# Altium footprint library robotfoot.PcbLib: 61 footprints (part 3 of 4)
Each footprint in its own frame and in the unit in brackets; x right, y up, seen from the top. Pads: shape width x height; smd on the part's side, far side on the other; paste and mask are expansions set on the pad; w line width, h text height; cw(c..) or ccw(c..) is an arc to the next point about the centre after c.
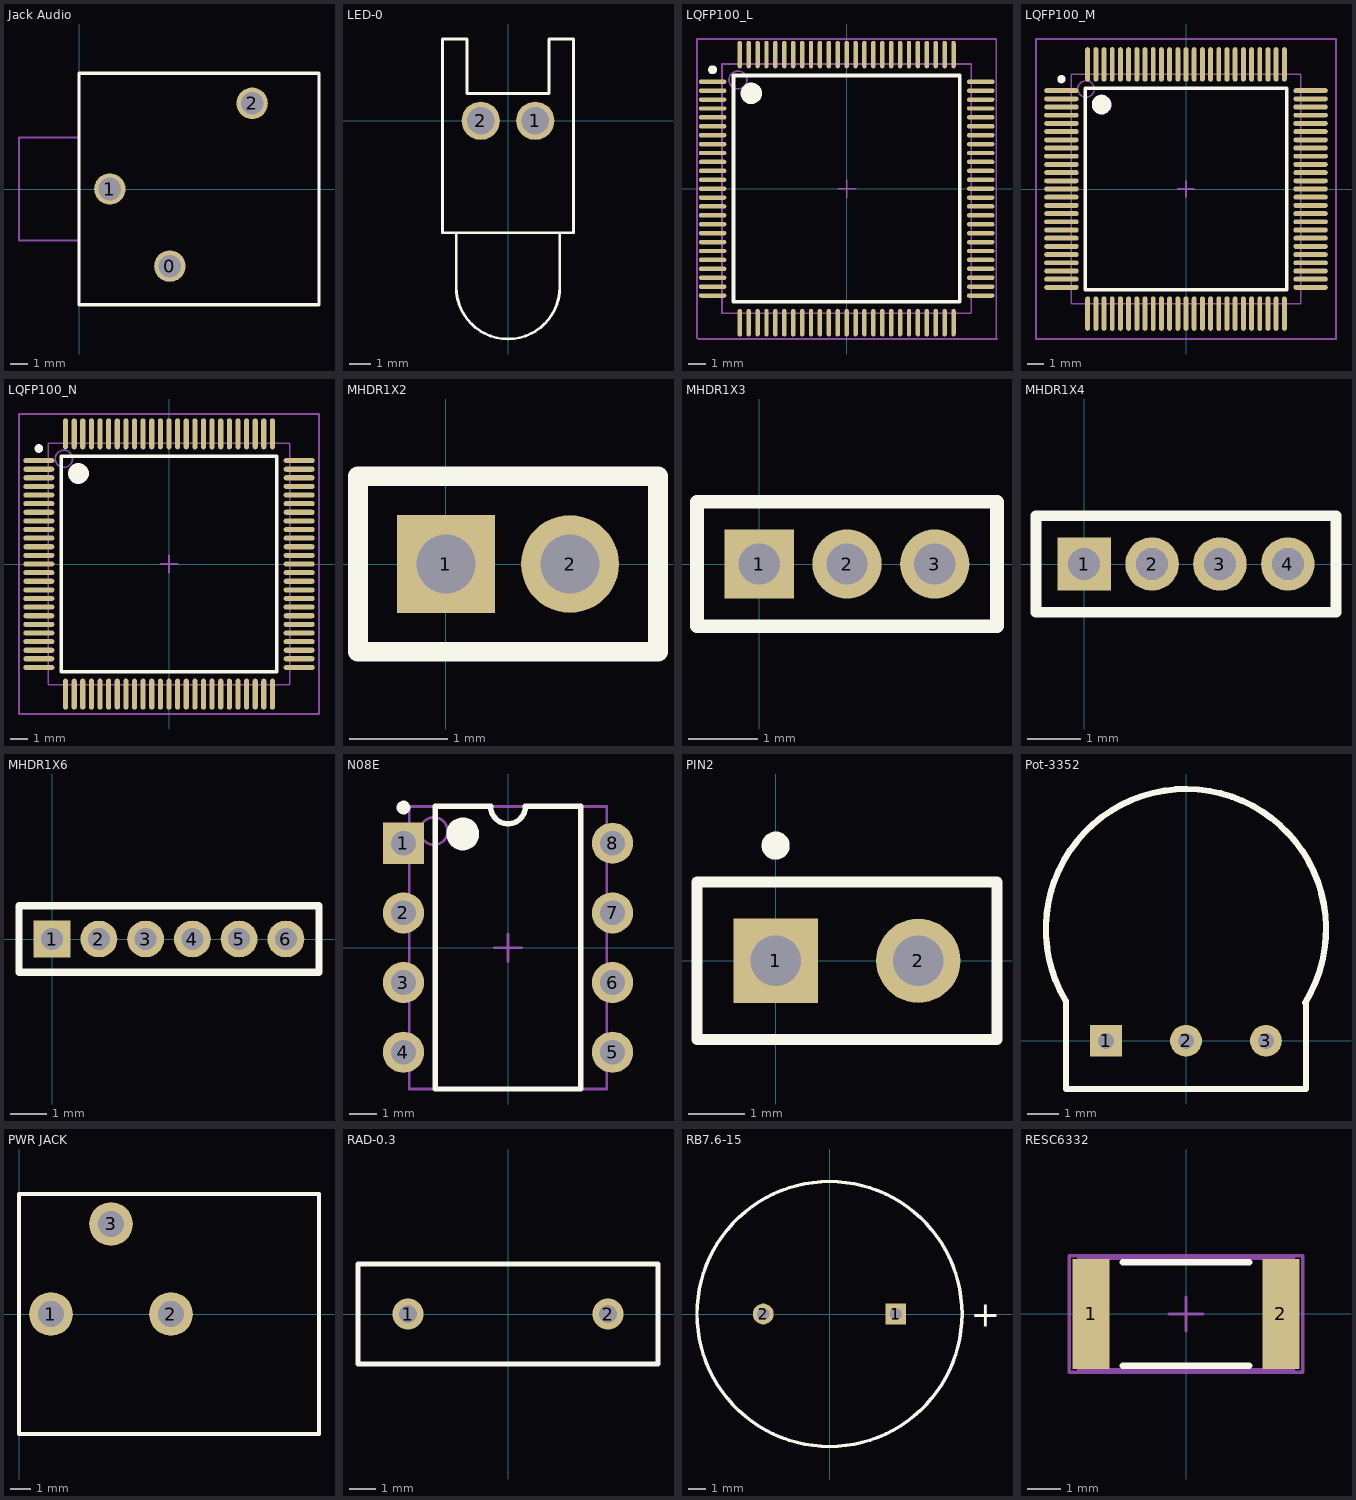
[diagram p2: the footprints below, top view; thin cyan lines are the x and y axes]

## Jack Audio [mil] "Connector; Stereo Jack 3.5mm"
height 157.48
pads (3):
  round 72 hole 52: 0(208.66,-177.17) 1(70.87,0) 2(397.64,196.85)
Top Overlay:
  lines w7.87: 0,-265.75 0,265.75 551.18,265.75 551.18,-265.75 0,-265.75
Mechanical 13:
  lines w3.94: -137.8,-118.11 0,-118.11 0,-265.75 551.18,-265.75 551.18,265.75 0,265.75 0,118.11 -137.8,118.11 -137.8,-118.11

## LED-0 [mil] "LED; 2 Leads"
pads (2):
  round 70 hole 50: 1(50,0) 2(-50,0)
Top Overlay:
  lines w5: -95,-205 -95,-305 ccw(c0,-305) 95,-305 95,-205 ; -120,-205 120,-205 120,150 75,150 75,50 -75,50 -75,150 -120,150 -120,-205

## LQFP100_L [mm] "Thin QFP, 100-Leads, Body 14x14mm, Pitch 0.5mm, IPC High Density"
height 1.6
pads (100):
  oval 1.55x0.25 smd: 1(-7.525,6) 2(-7.525,5.5) 3(-7.525,5) 4(-7.525,4.5) 5(-7.525,4) 6(-7.525,3.5) 7(-7.525,3) 8(-7.525,2.5) 9(-7.525,2) 10(-7.525,1.5) 11(-7.525,1) 12(-7.525,0.5) 13(-7.525,0) 14(-7.525,-0.5) 15(-7.525,-1) 16(-7.525,-1.5) 17(-7.525,-2) 18(-7.525,-2.5) 19(-7.525,-3) 20(-7.525,-3.5) 21(-7.525,-4) 22(-7.525,-4.5) 23(-7.525,-5) 24(-7.525,-5.5) 25(-7.525,-6) 51(7.525,-6) 52(7.525,-5.5) 53(7.525,-5) 54(7.525,-4.5) 55(7.525,-4) 56(7.525,-3.5) 57(7.525,-3) 58(7.525,-2.5) 59(7.525,-2) 60(7.525,-1.5) 61(7.525,-1) 62(7.525,-0.5) 63(7.525,0) 64(7.525,0.5) 65(7.525,1) 66(7.525,1.5) 67(7.525,2) 68(7.525,2.5) 69(7.525,3) 70(7.525,3.5) 71(7.525,4) 72(7.525,4.5) 73(7.525,5) 74(7.525,5.5) 75(7.525,6)
  oval 0.25x1.55 smd: 26(-6,-7.525) 27(-5.5,-7.525) 28(-5,-7.525) 29(-4.5,-7.525) 30(-4,-7.525) 31(-3.5,-7.525) 32(-3,-7.525) 33(-2.5,-7.525) 34(-2,-7.525) 35(-1.5,-7.525) 36(-1,-7.525) 37(-0.5,-7.525) 38(0,-7.525) 39(0.5,-7.525) 40(1,-7.525) 41(1.5,-7.525) 42(2,-7.525) 43(2.5,-7.525) 44(3,-7.525) 45(3.5,-7.525) 46(4,-7.525) 47(4.5,-7.525) 48(5,-7.525) 49(5.5,-7.525) 50(6,-7.525) 76(6,7.525) 77(5.5,7.525) 78(5,7.525) 79(4.5,7.525) 80(4,7.525) 81(3.5,7.525) 82(3,7.525) 83(2.5,7.525) 84(2,7.525) 85(1.5,7.525) 86(1,7.525) 87(0.5,7.525) 88(0,7.525) 89(-0.5,7.525) 90(-1,7.525) 91(-1.5,7.525) 92(-2,7.525) 93(-2.5,7.525) 94(-3,7.525) 95(-3.5,7.525) 96(-4,7.525) 97(-4.5,7.525) 98(-5,7.525) 99(-5.5,7.525) 100(-6,7.525)
Top Overlay:
  circle w0.25: c-7.525,6.675 r0.125
  circle w0.6: c-5.35,5.35 r0.3
  lines w0.2: -6.35,-6.35 -6.35,6.35 6.35,6.35 6.35,-6.35 -6.35,-6.35
Mechanical 13:
  circle w0.1: c-6.1,6.1 r0.5
  lines w0.1: -7,-7 -7,7 7,7 7,-7 -7,-7
Mechanical 15:
  lines w0.1: -8.4,-8.4 -8.4,8.4 8.4,8.4 8.4,-8.4 ; -8.36,-8.44 8.44,-8.44 ; -0.5,0 0.5,0 ; 0,-0.5 0,0.5
3D body: height 1.6, standoff 0, extent -7,-7 7,7

## LQFP100_M [mm] "Thin QFP, 100-Leads, Body 14x14mm, Pitch 0.5mm, IPC Low Density"
height 1.6
pads (100):
  oval 2.1x0.3 smd: 1(-7.6,6) 2(-7.6,5.5) 3(-7.6,5) 4(-7.6,4.5) 5(-7.6,4) 6(-7.6,3.5) 7(-7.6,3) 8(-7.6,2.5) 9(-7.6,2) 10(-7.6,1.5) 11(-7.6,1) 12(-7.6,0.5) 13(-7.6,0) 14(-7.6,-0.5) 15(-7.6,-1) 16(-7.6,-1.5) 17(-7.6,-2) 18(-7.6,-2.5) 19(-7.6,-3) 20(-7.6,-3.5) 21(-7.6,-4) 22(-7.6,-4.5) 23(-7.6,-5) 24(-7.6,-5.5) 25(-7.6,-6) 51(7.6,-6) 52(7.6,-5.5) 53(7.6,-5) 54(7.6,-4.5) 55(7.6,-4) 56(7.6,-3.5) 57(7.6,-3) 58(7.6,-2.5) 59(7.6,-2) 60(7.6,-1.5) 61(7.6,-1) 62(7.6,-0.5) 63(7.6,0) 64(7.6,0.5) 65(7.6,1) 66(7.6,1.5) 67(7.6,2) 68(7.6,2.5) 69(7.6,3) 70(7.6,3.5) 71(7.6,4) 72(7.6,4.5) 73(7.6,5) 74(7.6,5.5) 75(7.6,6)
  oval 0.3x2.1 smd: 26(-6,-7.6) 27(-5.5,-7.6) 28(-5,-7.6) 29(-4.5,-7.6) 30(-4,-7.6) 31(-3.5,-7.6) 32(-3,-7.6) 33(-2.5,-7.6) 34(-2,-7.6) 35(-1.5,-7.6) 36(-1,-7.6) 37(-0.5,-7.6) 38(0,-7.6) 39(0.5,-7.6) 40(1,-7.6) 41(1.5,-7.6) 42(2,-7.6) 43(2.5,-7.6) 44(3,-7.6) 45(3.5,-7.6) 46(4,-7.6) 47(4.5,-7.6) 48(5,-7.6) 49(5.5,-7.6) 50(6,-7.6) 76(6,7.6) 77(5.5,7.6) 78(5,7.6) 79(4.5,7.6) 80(4,7.6) 81(3.5,7.6) 82(3,7.6) 83(2.5,7.6) 84(2,7.6) 85(1.5,7.6) 86(1,7.6) 87(0.5,7.6) 88(0,7.6) 89(-0.5,7.6) 90(-1,7.6) 91(-1.5,7.6) 92(-2,7.6) 93(-2.5,7.6) 94(-3,7.6) 95(-3.5,7.6) 96(-4,7.6) 97(-4.5,7.6) 98(-5,7.6) 99(-5.5,7.6) 100(-6,7.6)
Top Overlay:
  circle w0.6: c-5.15,5.15 r0.3
  circle w0.25: c-7.6,6.7 r0.125
  lines w0.2: -6.15,-6.15 6.15,-6.15 6.15,6.15 -6.15,6.15 -6.15,-6.15
Mechanical 13:
  circle w0.1: c-6.1,6.1 r0.5
  lines w0.1: -7,-7 7,-7 7,7 -7,7 -7,-7
Mechanical 15:
  lines w0.1: -0.5,0 0.5,0 ; 0,-0.5 0,0.5 ; -9.15,-9.15 9.15,-9.15 9.15,9.15 -9.15,9.15 -9.15,-9.15
3D body: height 1.6, standoff 0, extent -7,-7 7,7

## LQFP100_N [mm] "Thin QFP, 100-Leads, Body 14x14mm, Pitch 0.5mm, IPC Medium Density"
height 1.6
pads (100):
  oval 1.8x0.3 smd: 1(-7.55,6) 2(-7.55,5.5) 3(-7.55,5) 4(-7.55,4.5) 5(-7.55,4) 6(-7.55,3.5) 7(-7.55,3) 8(-7.55,2.5) 9(-7.55,2) 10(-7.55,1.5) 11(-7.55,1) 12(-7.55,0.5) 13(-7.55,0) 14(-7.55,-0.5) 15(-7.55,-1) 16(-7.55,-1.5) 17(-7.55,-2) 18(-7.55,-2.5) 19(-7.55,-3) 20(-7.55,-3.5) 21(-7.55,-4) 22(-7.55,-4.5) 23(-7.55,-5) 24(-7.55,-5.5) 25(-7.55,-6) 51(7.55,-6) 52(7.55,-5.5) 53(7.55,-5) 54(7.55,-4.5) 55(7.55,-4) 56(7.55,-3.5) 57(7.55,-3) 58(7.55,-2.5) 59(7.55,-2) 60(7.55,-1.5) 61(7.55,-1) 62(7.55,-0.5) 63(7.55,0) 64(7.55,0.5) 65(7.55,1) 66(7.55,1.5) 67(7.55,2) 68(7.55,2.5) 69(7.55,3) 70(7.55,3.5) 71(7.55,4) 72(7.55,4.5) 73(7.55,5) 74(7.55,5.5) 75(7.55,6)
  oval 0.3x1.8 smd: 26(-6,-7.55) 27(-5.5,-7.55) 28(-5,-7.55) 29(-4.5,-7.55) 30(-4,-7.55) 31(-3.5,-7.55) 32(-3,-7.55) 33(-2.5,-7.55) 34(-2,-7.55) 35(-1.5,-7.55) 36(-1,-7.55) 37(-0.5,-7.55) 38(0,-7.55) 39(0.5,-7.55) 40(1,-7.55) 41(1.5,-7.55) 42(2,-7.55) 43(2.5,-7.55) 44(3,-7.55) 45(3.5,-7.55) 46(4,-7.55) 47(4.5,-7.55) 48(5,-7.55) 49(5.5,-7.55) 50(6,-7.55) 76(6,7.55) 77(5.5,7.55) 78(5,7.55) 79(4.5,7.55) 80(4,7.55) 81(3.5,7.55) 82(3,7.55) 83(2.5,7.55) 84(2,7.55) 85(1.5,7.55) 86(1,7.55) 87(0.5,7.55) 88(0,7.55) 89(-0.5,7.55) 90(-1,7.55) 91(-1.5,7.55) 92(-2,7.55) 93(-2.5,7.55) 94(-3,7.55) 95(-3.5,7.55) 96(-4,7.55) 97(-4.5,7.55) 98(-5,7.55) 99(-5.5,7.55) 100(-6,7.55)
Top Overlay:
  circle w0.6: c-5.25,5.25 r0.3
  circle w0.25: c-7.55,6.7 r0.125
  lines w0.2: -6.25,-6.25 6.25,-6.25 6.25,6.25 -6.25,6.25 -6.25,-6.25
Mechanical 13:
  circle w0.1: c-6.1,6.1 r0.5
  lines w0.1: -7,-7 7,-7 7,7 -7,7 -7,-7
Mechanical 15:
  lines w0.1: -0.5,0 0.5,0 ; 0,-0.5 0,0.5 ; -8.7,-8.7 8.7,-8.7 8.7,8.7 -8.7,8.7 -8.7,-8.7
3D body: height 1.6, standoff 0, extent -7,-7 7,7

## MHDR1X2 [mm] "Connector; Header; 2 Position"
pads (2):
  rect 1x1 hole 0.6: 1(0,0)
  round 1 hole 0.6: 2(1.27,0)
Top Overlay:
  lines w0.2: -0.9,-0.9 -0.9,0.9 2.17,0.9 2.17,-0.9 -0.9,-0.9

## MHDR1X3 [mm] "Connector; Header; 3 Position"
pads (3):
  rect 1x1 hole 0.6: 1(0,0)
  round 1 hole 0.6: 2(1.27,0) 3(2.54,0)
Top Overlay:
  lines w0.2: -0.9,-0.9 -0.9,0.9 3.44,0.9 3.44,-0.9 -0.9,-0.9

## MHDR1X4 [mm] "Connector; Header; 4 Position"
pads (4):
  rect 1x1 hole 0.6: 1(0,0)
  round 1 hole 0.6: 2(1.27,0) 3(2.54,0) 4(3.81,0)
Top Overlay:
  lines w0.2: -0.9,-0.9 4.71,-0.9 4.71,0.9 -0.9,0.9 -0.9,-0.9

## MHDR1X6 [mm] "Connector; Header; 6 Position"
pads (6):
  rect 1x1 hole 0.6: 1(0,0)
  round 1 hole 0.6: 2(1.27,0) 3(2.54,0) 4(3.81,0) 5(5.08,0) 6(6.35,0)
Top Overlay:
  lines w0.2: -0.9,-0.9 7.25,-0.9 7.25,0.9 -0.9,0.9 -0.9,-0.9

## N08E [mm] "DIP, 8-Leads, Row Spacing 7.62mm, Pitch 2.54mm, Body 9.91x6.35mm"
height 5.34
pads (8):
  rect 1.5x1.5 hole 0.9: 1(-3.81,3.81)
  round 1.5 hole 0.9: 2(-3.81,1.27) 3(-3.81,-1.27) 4(-3.81,-3.81) 5(3.81,-3.81) 6(3.81,-1.27) 7(3.81,1.27) 8(3.81,3.81)
Top Overlay:
  circle w0.6: c-1.65,4.15 r0.3
  circle w0.25: c-3.81,5.11 r0.125
  lines w0.2: -2.65,-5.15 2.65,-5.15 2.65,5.15 0.635,5.15 cw(c0,5.15) -0.635,5.15 -2.65,5.15 -2.65,-5.15
Mechanical 13:
  circle w0.1: c-2.7,4.25 r0.5
  lines w0.1: -3.6,-5.15 3.6,-5.15 3.6,5.15 -3.6,5.15 -3.6,-5.15
Mechanical 15:
  lines w0.1: -0.5,0 0.5,0 ; 0,-0.5 0,0.5
3D body: height 5.34, standoff 0, extent -3.6,-5.15 3.6,5.15

## PIN2 [mm] "Photosensitive Diode; 2 Leads"
pads (2):
  rect 1.5x1.5 hole 0.9: 1(0,0)
  round 1.5 hole 0.9: 2(2.54,0)
Top Overlay:
  circle w0.25: c0,2.05 r0.125
  lines w0.2: -1.4,-1.4 3.94,-1.4 3.94,1.4 -1.4,1.4 -1.4,-1.4

## Pot-3352 [mm] "Thru-Hole; 3 Leads"
pads (3):
  rect 1.01x1.01 hole 0.51: 1(-2.54,0)
  round 1.01 hole 0.51: 2(0,0) 3(2.54,0)
Top Overlay:
  lines w0.2: -3.818,1.265 cw(c0,3.55) 3.787,1.214 ; -3.81,1.2 -3.81,-1.53 3.81,-1.53 3.81,1.2

## PWR JACK [mil]
pads (3):
  round 86 hole 52: 1(62.99,0) 2(299.21,0) 3(181.1,177.17)
Top Overlay:
  lines w7.87: 0,-236.22 0,236.22 590.55,236.22 590.55,-236.22 0,-236.22

## RAD-0.3 [mm] "Radial Cap, Thru-Hole; 2 Leads; 0.3 in Pin Spacing"
height 6
pads (2):
  round 1.2 hole 0.7: 1(-3.81,0) 2(3.81,0)
Top Overlay:
  lines w0.2: -5.715,-1.905 -5.715,1.905 5.715,1.905 5.715,-1.905 -5.715,-1.905

## RB7.6-15 [mm] "Polarized Capacitor (Radial); 2 Leads"
pads (2):
  rect 1.2x1.2 hole 0.7: 1(3.81,0)
  round 1.2 hole 0.7: 2(-3.81,0)
Top Overlay:
  circle w0.2: c0,0 r7.62
  text "+" at 8.132,-0.737 h1.5

## RESC6332 [mm] "Chip Resistor, Body 6.3x3.2mm, IPC High Density"
height 0.9
pads (2):
  rect 1.1x3.3 smd: 1(-2.85,0) 2(2.85,0)
Top Overlay:
  lines w0.2: -1.9,-1.55 1.9,-1.55 ; -1.9,1.55 1.9,1.55
Mechanical 13:
  lines w0.1: -3.225,-1.675 -3.225,1.675 3.225,1.675 3.225,-1.675 -3.225,-1.675
Mechanical 15:
  lines w0.1: -0.5,0 0.5,0 ; 0,-0.5 0,0.5 ; -3.5,-1.75 -3.5,1.75 3.5,1.75 3.5,-1.75 -3.5,-1.75
3D body: height 0.9, standoff 0, extent -3.225,-1.675 3.225,1.675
